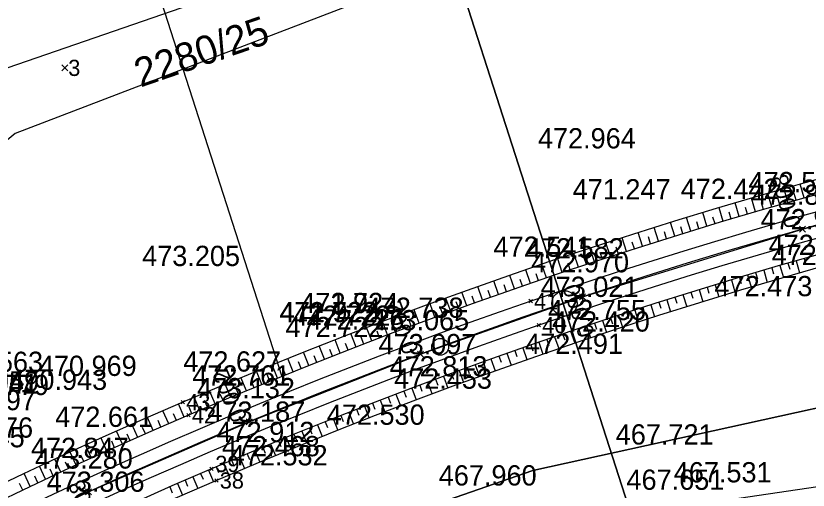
# Model space of a CAD drawing. Extents: x -758836 to -757729, y -1175316 to -1174366.
# Drawn here: x -758331.65 to -758284.69, y -1174791.36 to -1174763.28 of the extents above; entities that cross this region are included whole.
import ezdxf

# ---------------------------------------------------------------- set-up
doc = ezdxf.new("R2010")
doc.units = 0
for name, color, linetype in [('_NOR-body-stávající osa', 7, 'Continuous'), ('_NOR-návrh tenká', 7, 'Continuous'), ('_NOR-osa', 7, 'Continuous'), ('_NOR-pomocná', 7, 'Continuous'), ('_NOR-popis', 7, 'Continuous'), ('_NOR-posuny', 7, 'Continuous'), ('_NOR-svahy', 7, 'Continuous'), ('_NOR-vytyčení', 7, 'Continuous'), ('_vytyčený bod', 7, 'Continuous'), ('G_Obvod stavby', 7, 'Continuous'), ('Hranice parcel', 7, 'Continuous'), ('Parcelní čísla', 7, 'Continuous'), ('Vrstva 1', 7, 'Continuous'), ('Vrstva 61', 7, 'Continuous'), ('Vrstva 7', 7, 'Continuous')]:
    doc.layers.add(name, color=color, linetype=linetype)

# ---------------------------------------------------------------- blocks, each defined once
blk = doc.blocks.new('C513')
at = {"layer": 'Vrstva 7'}
blk.add_circle((0, 0), 0.75, dxfattribs=at)
blk = doc.blocks.new('POINT_DISPLAY')
for p, q in [((-0.175, -0.175), (0.175, 0.175)), ((-0.175, 0.175), (0.175, -0.175))]:
    blk.add_line(p, q)

msp = doc.modelspace()

# ---------------------------------------------------------------- linework, layer by layer
at = {"layer": '_NOR-návrh tenká'}
for radius, start, end in [(295.6, 97.09776, 129.28488), (294.75, 97.0979, 129.28474), (293.75, 97.09807, 120.96729), (292.25, 97.09832, 120.96729), (291.3, 97.09848, 129.28417), (290.55, 97.09861, 129.28404)]:
    msp.add_arc((-758205.34, -1175057.864), radius, start, end, dxfattribs=at)
at = {"layer": '_NOR-osa'}
msp.add_arc((-758205.34, -1175057.864), 293, 97.09819, 129.28445, dxfattribs=at)
at = {"layer": '_NOR-pomocná'}
for points in [[(-758317.652, -1174723.031), (-758217.708, -1174690.839), (-758172.179, -1174832.187), (-758272.123, -1174864.38)], [(-758417.595, -1174755.224), (-758317.652, -1174723.031), (-758272.123, -1174864.38), (-758372.066, -1174896.572)]]:
    msp.add_lwpolyline(points, close=True, dxfattribs=at)
at = {"layer": '_NOR-popis'}
msp.add_lwpolyline([(-758320.015, -1174740.786), (-758329.058, -1174743.698), (-758315.875, -1174784.625)], dxfattribs=at)
msp.add_circle((-758306.497, -1174782.88), 0.5, dxfattribs=at)
msp.add_circle((-758306.497, -1174782.88), 0.5, dxfattribs=at)
at = {"layer": '_NOR-svahy'}
for points in [[(-758284.924, -1174774.062), (-758285.154, -1174773.243)], [(-758286.848, -1174774.608), (-758287.083, -1174773.791)], [(-758285.887, -1174774.333), (-758286.119, -1174773.516)], [(-758285.405, -1174774.197), (-758285.521, -1174773.788)], [(-758287.809, -1174774.886), (-758288.046, -1174774.07)], [(-758286.367, -1174774.47), (-758286.484, -1174774.062)], [(-758289.727, -1174775.452), (-758289.97, -1174774.638)], [(-758288.768, -1174775.168), (-758289.009, -1174774.352)], [(-758288.289, -1174775.027), (-758288.408, -1174774.619)], [(-758287.328, -1174774.747), (-758287.447, -1174774.339)], [(-758291.641, -1174776.031), (-758291.89, -1174775.219)], [(-758290.684, -1174775.74), (-758290.931, -1174774.927)], [(-758290.206, -1174775.596), (-758290.328, -1174775.189)], [(-758289.248, -1174775.31), (-758289.369, -1174774.902)], [(-758292.597, -1174776.326), (-758292.848, -1174775.514)], [(-758291.163, -1174775.885), (-758291.287, -1174775.479)], [(-758294.505, -1174776.924), (-758294.762, -1174776.114)], [(-758293.551, -1174776.623), (-758293.806, -1174775.812)], [(-758293.074, -1174776.474), (-758293.201, -1174776.069)], [(-758292.119, -1174776.178), (-758292.244, -1174775.772)], [(-758295.458, -1174777.229), (-758295.718, -1174776.419)], [(-758294.028, -1174776.774), (-758294.156, -1174776.368)], [(-758297.36, -1174777.846), (-758297.625, -1174777.039)], [(-758296.409, -1174777.536), (-758296.672, -1174776.727)], [(-758295.934, -1174777.382), (-758296.064, -1174776.977)], [(-758294.982, -1174777.076), (-758295.111, -1174776.671)], [(-758298.309, -1174778.16), (-758298.577, -1174777.354)], [(-758297.835, -1174778.003), (-758297.968, -1174777.599)], [(-758296.885, -1174777.691), (-758297.017, -1174777.287)], [(-758300.205, -1174778.798), (-758300.479, -1174777.993)], [(-758299.258, -1174778.477), (-758299.529, -1174777.672)], [(-758298.784, -1174778.318), (-758298.918, -1174777.915)], [(-758286.364, -1174778.059), (-758286.155, -1174778.779)], [(-758285.883, -1174777.92), (-758285.78, -1174778.281)], [(-758285.403, -1174777.783), (-758285.196, -1174778.504)], [(-758284.922, -1174777.646), (-758284.819, -1174778.006)], [(-758301.151, -1174779.121), (-758301.428, -1174778.317)], [(-758299.732, -1174778.637), (-758299.868, -1174778.234)], [(-758287.803, -1174778.48), (-758287.697, -1174778.84)], [(-758287.324, -1174778.339), (-758287.113, -1174779.059)], [(-758286.844, -1174778.199), (-758286.739, -1174778.559)], [(-758303.041, -1174779.778), (-758303.322, -1174778.976)], [(-758302.097, -1174779.448), (-758302.376, -1174778.645)], [(-758301.624, -1174779.284), (-758301.763, -1174778.882)], [(-758300.678, -1174778.959), (-758300.816, -1174778.557)], [(-758289.241, -1174778.908), (-758289.025, -1174779.627)], [(-758288.762, -1174778.765), (-758288.655, -1174779.124)], [(-758288.283, -1174778.622), (-758288.069, -1174779.341)], [(-758303.983, -1174780.111), (-758304.268, -1174779.31)], [(-758302.569, -1174779.612), (-758302.709, -1174779.211)], [(-758290.676, -1174779.344), (-758290.566, -1174779.703)], [(-758290.198, -1174779.198), (-758289.979, -1174779.915)], [(-758289.72, -1174779.053), (-758289.611, -1174779.412)], [(-758304.925, -1174780.447), (-758305.212, -1174779.647)], [(-758304.454, -1174780.278), (-758304.597, -1174779.878)], [(-758303.512, -1174779.944), (-758303.654, -1174779.543)], [(-758292.586, -1174779.937), (-758292.474, -1174780.294)], [(-758292.109, -1174779.787), (-758291.886, -1174780.503)], [(-758291.632, -1174779.639), (-758291.521, -1174779.997)], [(-758291.154, -1174779.491), (-758290.933, -1174780.208)], [(-758306.805, -1174781.129), (-758307.098, -1174780.331)], [(-758305.866, -1174780.786), (-758306.156, -1174779.987)], [(-758305.396, -1174780.616), (-758305.54, -1174780.216)], [(-758294.016, -1174780.389), (-758293.788, -1174781.104)], [(-758293.54, -1174780.238), (-758293.426, -1174780.595)], [(-758293.063, -1174780.087), (-758292.837, -1174780.802)], [(-758307.744, -1174781.475), (-758308.039, -1174780.678)], [(-758306.336, -1174780.957), (-758306.481, -1174780.558)], [(-758295.444, -1174780.85), (-758295.328, -1174781.206)], [(-758294.968, -1174780.696), (-758294.738, -1174781.409)], [(-758294.493, -1174780.542), (-758294.378, -1174780.899)], [(-758308.681, -1174781.824), (-758308.979, -1174781.028)], [(-758308.212, -1174781.649), (-758308.361, -1174781.251)], [(-758307.275, -1174781.301), (-758307.422, -1174780.903)], [(-758296.869, -1174781.317), (-758296.634, -1174782.029)], [(-758296.394, -1174781.161), (-758296.277, -1174781.517)], [(-758295.919, -1174781.005), (-758295.686, -1174781.718)], [(-758310.551, -1174782.531), (-758310.855, -1174781.737)], [(-758309.617, -1174782.176), (-758309.917, -1174781.381)], [(-758309.149, -1174782), (-758309.299, -1174781.602)], [(-758298.292, -1174781.792), (-758298.172, -1174782.148)], [(-758297.818, -1174781.633), (-758297.58, -1174782.344)], [(-758297.344, -1174781.475), (-758297.225, -1174781.831)], [(-758311.485, -1174782.89), (-758311.791, -1174782.097)], [(-758310.084, -1174782.353), (-758310.235, -1174781.956)], [(-758299.712, -1174782.275), (-758299.469, -1174782.984)], [(-758299.239, -1174782.113), (-758299.118, -1174782.468)], [(-758298.766, -1174781.952), (-758298.525, -1174782.663)], [(-758312.417, -1174783.252), (-758312.726, -1174782.46)], [(-758311.951, -1174783.07), (-758312.105, -1174782.674)], [(-758311.018, -1174782.71), (-758311.171, -1174782.314)], [(-758301.13, -1174782.764), (-758301.007, -1174783.118)], [(-758300.658, -1174782.6), (-758300.412, -1174783.309)], [(-758300.185, -1174782.437), (-758300.063, -1174782.792)], [(-758314.278, -1174783.984), (-758314.592, -1174783.195)], [(-758313.348, -1174783.616), (-758313.66, -1174782.826)], [(-758312.883, -1174783.434), (-758313.038, -1174783.038)], [(-758302.074, -1174783.095), (-758301.95, -1174783.448)], [(-758301.602, -1174782.929), (-758301.354, -1174783.637)], [(-758315.207, -1174784.356), (-758315.523, -1174783.567)], [(-758313.813, -1174783.8), (-758313.97, -1174783.405)], [(-758303.488, -1174783.597), (-758303.235, -1174784.303)], [(-758303.017, -1174783.428), (-758302.891, -1174783.782)], [(-758302.546, -1174783.261), (-758302.295, -1174783.968)], [(-758316.134, -1174784.73), (-758316.453, -1174783.942)], [(-758315.67, -1174784.542), (-758315.83, -1174784.148)], [(-758314.742, -1174784.17), (-758314.9, -1174783.775)], [(-758304.899, -1174784.106), (-758304.77, -1174784.458)], [(-758304.429, -1174783.935), (-758304.173, -1174784.64)], [(-758303.958, -1174783.765), (-758303.831, -1174784.118)], [(-758317.06, -1174785.107), (-758317.382, -1174784.321)], [(-758316.597, -1174784.918), (-758316.758, -1174784.525)], [(-758306.307, -1174784.622), (-758306.047, -1174785.325)], [(-758305.838, -1174784.449), (-758305.708, -1174784.801)], [(-758305.368, -1174784.277), (-758305.111, -1174784.981)], [(-758318.908, -1174785.872), (-758319.236, -1174785.087)], [(-758317.985, -1174785.488), (-758318.31, -1174784.703)], [(-758317.522, -1174785.297), (-758317.684, -1174784.904)], [(-758307.244, -1174784.97), (-758306.982, -1174785.673)], [(-758306.776, -1174784.796), (-758306.645, -1174785.147)], [(-758319.83, -1174786.259), (-758320.16, -1174785.475)], [(-758318.447, -1174785.68), (-758318.61, -1174785.287)], [(-758308.648, -1174785.498), (-758308.515, -1174785.849)], [(-758308.181, -1174785.321), (-758307.916, -1174786.023)], [(-758307.713, -1174785.145), (-758307.581, -1174785.496)], [(-758320.751, -1174786.649), (-758321.084, -1174785.867)], [(-758319.369, -1174786.065), (-758319.534, -1174785.673)], [(-758310.049, -1174786.034), (-758309.78, -1174786.734)], [(-758309.583, -1174785.855), (-758309.448, -1174786.205)], [(-758309.116, -1174785.676), (-758308.848, -1174786.377)], [(-758321.671, -1174787.042), (-758322.006, -1174786.261)], [(-758321.211, -1174786.845), (-758321.378, -1174786.454)], [(-758320.291, -1174786.453), (-758320.457, -1174786.062)], [(-758310.982, -1174786.395), (-758310.71, -1174787.094)], [(-758310.516, -1174786.214), (-758310.38, -1174786.564)], [(-758322.589, -1174787.438), (-758322.927, -1174786.658)], [(-758322.13, -1174787.239), (-758322.298, -1174786.849)], [(-758312.378, -1174786.943), (-758312.241, -1174787.291)], [(-758311.913, -1174786.759), (-758311.639, -1174787.457)], [(-758311.448, -1174786.577), (-758311.311, -1174786.926)], [(-758324.421, -1174788.24), (-758324.764, -1174787.462)], [(-758323.506, -1174787.837), (-758323.846, -1174787.059)], [(-758323.047, -1174787.637), (-758323.217, -1174787.248)], [(-758313.308, -1174787.312), (-758313.169, -1174787.66)], [(-758312.843, -1174787.127), (-758312.566, -1174787.824)], [(-758325.335, -1174788.645), (-758325.681, -1174787.869)], [(-758323.963, -1174788.038), (-758324.134, -1174787.649)], [(-758314.7, -1174787.871), (-758314.418, -1174788.566)], [(-758314.236, -1174787.684), (-758314.096, -1174788.032)], [(-758313.772, -1174787.497), (-758313.493, -1174788.193)], [(-758326.248, -1174789.054), (-758326.596, -1174788.279)], [(-758324.878, -1174788.442), (-758325.051, -1174788.054)], [(-758315.626, -1174788.248), (-758315.342, -1174788.942)], [(-758315.163, -1174788.059), (-758315.021, -1174788.407)], [(-758327.159, -1174789.466), (-758327.51, -1174788.692)], [(-758326.704, -1174789.259), (-758326.879, -1174788.872)], [(-758325.792, -1174788.849), (-758325.965, -1174788.461)], [(-758317.013, -1174788.82), (-758316.869, -1174789.166)], [(-758316.551, -1174788.628), (-758316.264, -1174789.322)], [(-758316.088, -1174788.438), (-758315.946, -1174788.785)], [(-758328.069, -1174789.881), (-758328.423, -1174789.108)], [(-758327.614, -1174789.673), (-758327.79, -1174789.286)], [(-758317.936, -1174789.205), (-758317.791, -1174789.55)], [(-758317.474, -1174789.012), (-758317.186, -1174789.704)], [(-758328.977, -1174790.299), (-758329.334, -1174789.527)], [(-758328.523, -1174790.089), (-758328.701, -1174789.703)], [(-758319.317, -1174789.788), (-758319.024, -1174790.478)], [(-758318.857, -1174789.593), (-758318.711, -1174789.938)], [(-758318.397, -1174789.398), (-758318.105, -1174790.09)], [(-758329.884, -1174790.72), (-758330.244, -1174789.949)], [(-758329.431, -1174790.509), (-758329.61, -1174790.123)], [(-758320.237, -1174790.181), (-758319.941, -1174790.87)], [(-758319.777, -1174789.984), (-758319.63, -1174790.329)], [(-758330.79, -1174791.144), (-758331.152, -1174790.374)], [(-758330.337, -1174790.931), (-758330.518, -1174790.546)], [(-758321.155, -1174790.577), (-758320.857, -1174791.265)], [(-758320.696, -1174790.378), (-758320.548, -1174790.723)], [(-758331.242, -1174791.357), (-758331.424, -1174790.973)], [(-758322.53, -1174791.177), (-758322.379, -1174791.52)], [(-758322.072, -1174790.976), (-758321.772, -1174791.663)], [(-758321.614, -1174790.776), (-758321.464, -1174791.12)]]:
    msp.add_lwpolyline(points, dxfattribs=at)
at = {"layer": '_vytyčený bod'}
for p, q in [((-758328.741, -1174766.355), (-758328.841, -1174766.255)), ((-758328.741, -1174766.355), (-758328.641, -1174766.255)), ((-758328.741, -1174766.355), (-758328.841, -1174766.455)), ((-758328.741, -1174766.355), (-758328.641, -1174766.455)), ((-758301.134, -1174780.173), (-758301.234, -1174780.073)), ((-758301.134, -1174780.173), (-758301.234, -1174780.273)), ((-758301.134, -1174780.173), (-758301.034, -1174780.073)), ((-758301.134, -1174780.173), (-758301.034, -1174780.273)), ((-758300.646, -1174781.591), (-758300.746, -1174781.491)), ((-758300.646, -1174781.591), (-758300.746, -1174781.691)), ((-758300.646, -1174781.591), (-758300.546, -1174781.491)), ((-758300.646, -1174781.591), (-758300.546, -1174781.691)), ((-758321.748, -1174786.15), (-758321.848, -1174786.05)), ((-758321.748, -1174786.15), (-758321.648, -1174786.05)), ((-758321.748, -1174786.15), (-758321.848, -1174786.25)), ((-758321.748, -1174786.15), (-758321.648, -1174786.25)), ((-758321.413, -1174786.931), (-758321.513, -1174786.831)), ((-758321.413, -1174786.931), (-758321.513, -1174787.031)), ((-758321.413, -1174786.931), (-758321.313, -1174786.831)), ((-758321.413, -1174786.931), (-758321.313, -1174787.031)), ((-758320.055, -1174790.103), (-758320.155, -1174790.003)), ((-758320.055, -1174790.103), (-758320.155, -1174790.203)), ((-758320.055, -1174790.103), (-758319.955, -1174790.003)), ((-758320.055, -1174790.103), (-758319.955, -1174790.203)), ((-758319.759, -1174790.792), (-758319.859, -1174790.692)), ((-758319.759, -1174790.792), (-758319.659, -1174790.692)), ((-758319.759, -1174790.792), (-758319.859, -1174790.892)), ((-758319.759, -1174790.792), (-758319.659, -1174790.892))]:
    msp.add_line(p, q, dxfattribs=at)
at = {"layer": 'G_Obvod stavby'}
msp.add_lwpolyline([(-758392.72, -1174840.756), (-758391.23, -1174838.56), (-758368.37, -1174821.64), (-758340.31, -1174807.33), (-758320.27, -1174796.89), (-758301, -1174790.21), (-758267.96, -1174782.93), (-758224.96, -1174775.27), (-758184.87, -1174772.83), (-758142.71, -1174770.26), (-758089.84, -1174768.68), (-758106.02, -1174731.44), (-758149.09, -1174725.67), (-758199.62, -1174726.6), (-758225.76, -1174732.36), (-758252.17, -1174738.18), (-758254.97, -1174739.34), (-758266.58, -1174744.16), (-758279.45, -1174749.49), (-758302.42, -1174759.02), (-758331.68, -1174770.24), (-758367.17, -1174799.81), (-758405.64, -1174832.2)], dxfattribs=at)
at = {"layer": 'Hranice parcel'}
for p, q in [((-758333.29, -1174766.74), (-758319.98, -1174762.15)), ((-758279.42, -1174790.47), (-758292.27, -1174792.38))]:
    msp.add_line(p, q, dxfattribs=at)
for points in [[(-758279.45, -1174749.49), (-758302.42, -1174759.02), (-758331.68, -1174770.24)], [(-758184.87, -1174772.83), (-758224.96, -1174775.27), (-758267.96, -1174782.93), (-758301, -1174790.21), (-758320.27, -1174796.89)]]:
    msp.add_lwpolyline(points, dxfattribs=at)
at = {"layer": 'Vrstva 1'}
msp.add_lwpolyline([(-758443.817, -1174881.252), (-758441.673, -1174879.1), (-758423.412, -1174860.854), (-758412.446, -1174850.23), (-758405.322, -1174843.614), (-758399.028, -1174837.996), (-758392.64, -1174832.554), (-758380.106, -1174822.693), (-758371.773, -1174816.721), (-758363.37, -1174811.125), (-758354.46, -1174805.649), (-758345.526, -1174800.592), (-758336.614, -1174795.909), (-758327.338, -1174791.462), (-758317.813, -1174787.314), (-758307.666, -1174783.315), (-758298.059, -1174779.921), (-758285.017, -1174775.914), (-758275.047, -1174773.289)], dxfattribs=at)

# ---------------------------------------------------------------- block references
at = {"layer": '_NOR-body-stávající osa'}
for p in [(-758285.017, -1174775.914), (-758298.059, -1174779.921), (-758307.666, -1174783.315), (-758317.813, -1174787.314), (-758327.338, -1174791.462)]:
    msp.add_blockref('POINT_DISPLAY', p, dxfattribs=at)
at = {"layer": '_NOR-vytyčení'}
msp.add_blockref('POINT_DISPLAY', (-758328.741, -1174766.355), dxfattribs=at)
at = {"layer": 'Vrstva 7', "rotation": 19.45750276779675}
msp.add_blockref('C513', (-758299.134, -1174780.301), dxfattribs=at)

# ---------------------------------------------------------------- texts
at = {"layer": '_NOR-posuny'}
for s, rotation, p in [('0,008', 105.7799, (-758285.087, -1174775.666)), ('0,000', 108.4482, (-758297.329, -1174782.11)), ('0,002', 110.4407, (-758307.754, -1174783.079)), ('0,002', 112.5736, (-758317.91, -1174787.081)), ('0,008', 114.6053, (-758326.373, -1174793.57))]:
    msp.add_text(s, height=0.9599, rotation=rotation, dxfattribs=at).set_placement(p)
at = {"layer": '_vytyčený bod'}
for s, height, p in [('3', 0.96, (-758328.541, -1174766.835)), ('3', 0.96, (-758328.541, -1174766.835)), ('41', 0.9599, (-758300.934, -1174780.653)), ('41', 0.9596, (-758300.934, -1174780.653)), ('40', 0.9599, (-758300.446, -1174782.071)), ('40', 0.9596, (-758300.446, -1174782.071)), ('43', 0.9599, (-758321.548, -1174786.63)), ('43', 0.9596, (-758321.548, -1174786.63)), ('42', 0.9599, (-758321.213, -1174787.411)), ('42', 0.9596, (-758321.213, -1174787.411)), ('39', 0.9599, (-758319.825, -1174790.291)), ('39', 0.9596, (-758319.825, -1174790.29)), ('38', 0.9599, (-758319.559, -1174791.272)), ('38', 0.9596, (-758319.559, -1174791.272))]:
    msp.add_text(s, height=height, dxfattribs=at).set_placement(p)
at = {"layer": 'Parcelní čísla'}
msp.add_text('2280/25', height=1.7, rotation=19, dxfattribs=at).set_placement((-758324.263, -1174767.523))
at = {"layer": 'Vrstva 61'}
for s, p in [('472.964', (-758300.704, -1174771.126)), ('472.442', (-758292.241, -1174774.119)), ('472.526', (-758288.221, -1174773.719)), ('471.247', (-758298.642, -1174774.147)), ('472.879', (-758288.038, -1174774.467)), ('472.909', (-758287.502, -1174775.914)), ('472.541', (-758303.336, -1174777.546)), ('472.582', (-758301.414, -1174777.642)), ('472.663', (-758287.032, -1174777.438)), ('473.205', (-758324.161, -1174778.092)), ('472.366', (-758286.853, -1174778.034)), ('472.970', (-758301.105, -1174778.466)), ('473.021', (-758300.544, -1174779.921)), ('472.473', (-758290.238, -1174779.88)), ('471.924', (-758314.786, -1174780.883)), ('472.724', (-758314.782, -1174780.88)), ('472.738', (-758310.911, -1174781.16)), ('472.722', (-758316.036, -1174781.426)), ('471.922', (-758316.006, -1174781.412)), ('472.722', (-758315.246, -1174781.632)), ('472.755', (-758300.102, -1174781.294)), ('472.726', (-758314.417, -1174781.852)), ('473.065', (-758310.581, -1174781.897)), ('472.420', (-758299.873, -1174781.976)), ('472.722', (-758315.663, -1174782.304)), ('473.097', (-758310.151, -1174783.315)), ('472.491', (-758301.463, -1174783.295)), ('471.563', (-758335.833, -1174784.364)), ('472.627', (-758321.723, -1174784.343)), ('470.969', (-758330.283, -1174784.601)), ('472.813', (-758309.495, -1174784.631)), ('472.761', (-758321.185, -1174785.171)), ('472.453', (-758309.229, -1174785.358)), ('470.741', (-758336.094, -1174785.655)), ('471.041', (-758336.094, -1174785.655)), ('470.959', (-758336.068, -1174785.524)), ('470.779', (-758335.484, -1174785.732)), ('470.943', (-758332.036, -1174785.428)), ('473.132', (-758320.906, -1174785.924)), ('471.597', (-758336.258, -1174786.632)), ('472.661', (-758329.314, -1174787.618)), ('473.187', (-758320.298, -1174787.314)), ('472.530', (-758313.22, -1174787.494)), ('470.976', (-758336.424, -1174788.256)), ('472.912', (-758319.755, -1174788.517)), ('467.721', (-758296.093, -1174788.664)), ('471.045', (-758336.923, -1174788.827)), ('472.847', (-758330.755, -1174789.464)), ('472.468', (-758319.435, -1174789.358)), ('473.280', (-758330.515, -1174790.089)), ('472.532', (-758318.971, -1174789.899)), ('467.531', (-758292.655, -1174790.905)), ('473.306', (-758329.823, -1174791.462)), ('467.960', (-758306.581, -1174791.09)), ('467.651', (-758295.456, -1174791.344))]:
    msp.add_text(s, height=1.2, dxfattribs=at).set_placement(p)

doc.saveas('drawing.dxf')
